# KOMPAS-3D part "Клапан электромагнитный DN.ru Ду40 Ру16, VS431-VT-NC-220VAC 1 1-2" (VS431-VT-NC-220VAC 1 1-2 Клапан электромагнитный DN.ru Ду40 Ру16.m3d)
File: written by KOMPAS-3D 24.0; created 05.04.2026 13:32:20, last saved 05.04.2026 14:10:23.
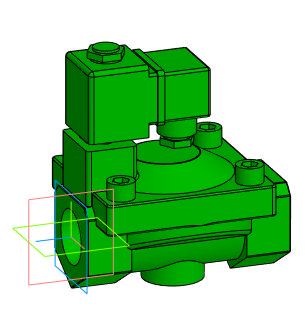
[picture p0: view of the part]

Document properties: Автор: artio; Полное имя файла: C:\Users\artio\OneDrive\Рабочий стол\Клапан электромагнитный DN.ru\VS431\VS431-VT-NC\VS431-VT-NC-220VAC\Ду40\VS431-VT-NC-220VAC 1 1-2 Клапан электромагнитный DN.ru Ду40 Ру16.m3d

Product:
- Body: Тело 1  | qty 1
    Масса: 3.859459
- Part/product: Клапан электромагнитный DN.ru Ду40 Ру16  | designation VS431-VT-NC-220VAC 1 1-2
    Масса: 2.285
    Раздел спецификации: Прочие изделия
    Примечание: D130-04716
    additional columns: ef56311e-7521-43dc-8291-0e6108b3d81d; artio; c; Шероховатость не задана; Да

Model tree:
1. Операция без истории:1

Expressions: VS431-VT-NC-220VAC 1 1-2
